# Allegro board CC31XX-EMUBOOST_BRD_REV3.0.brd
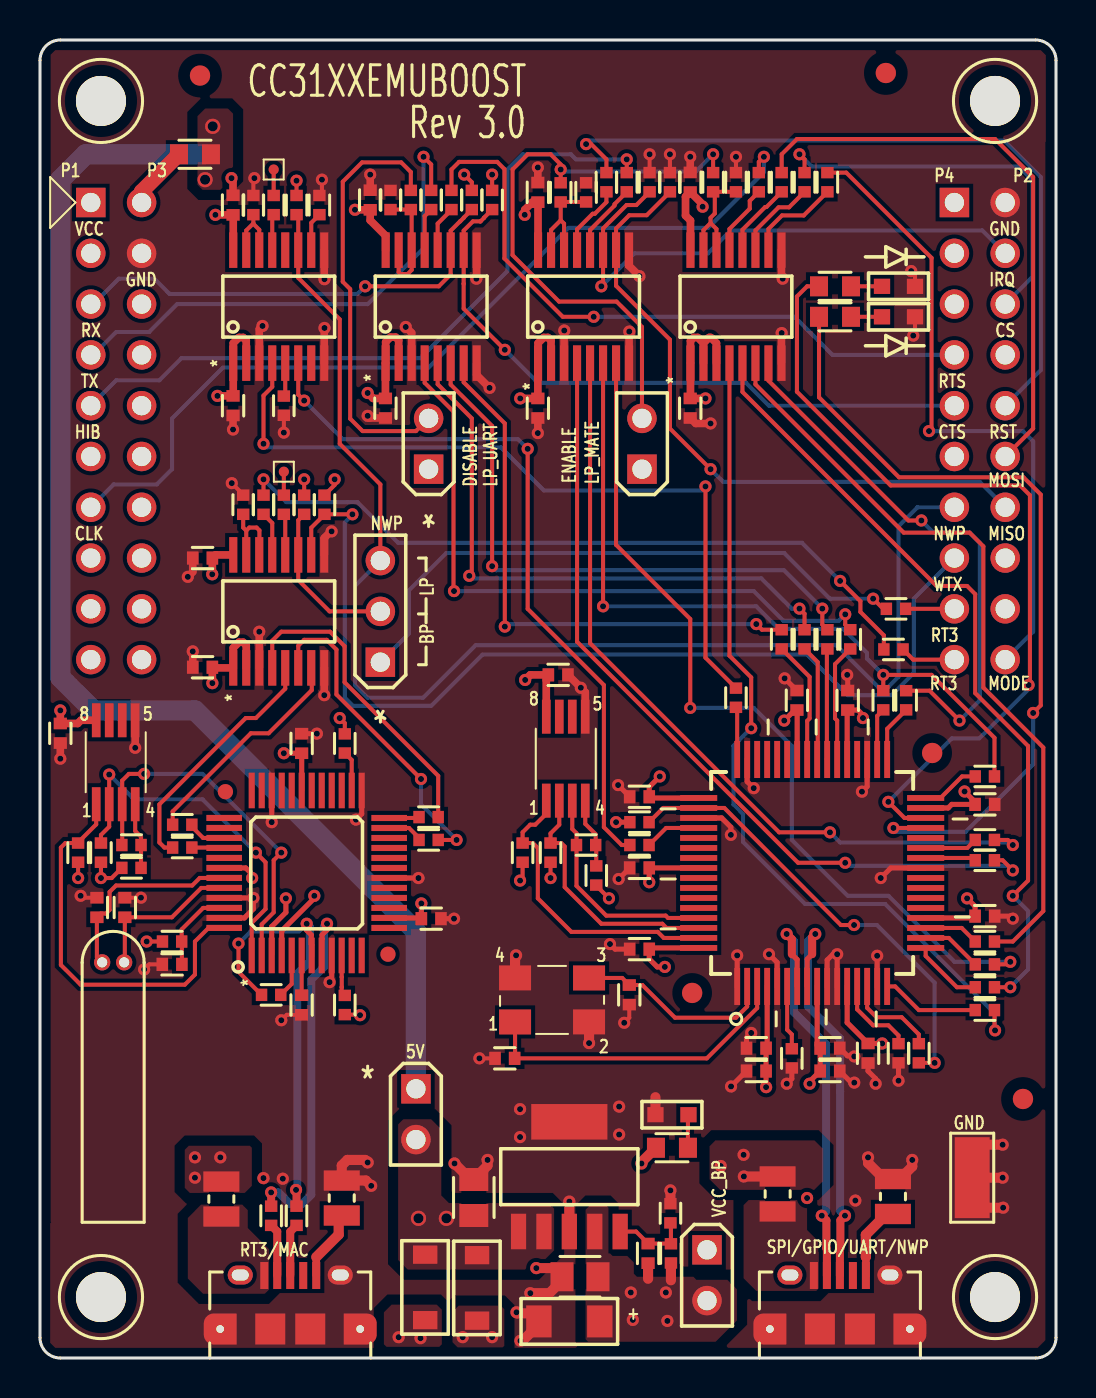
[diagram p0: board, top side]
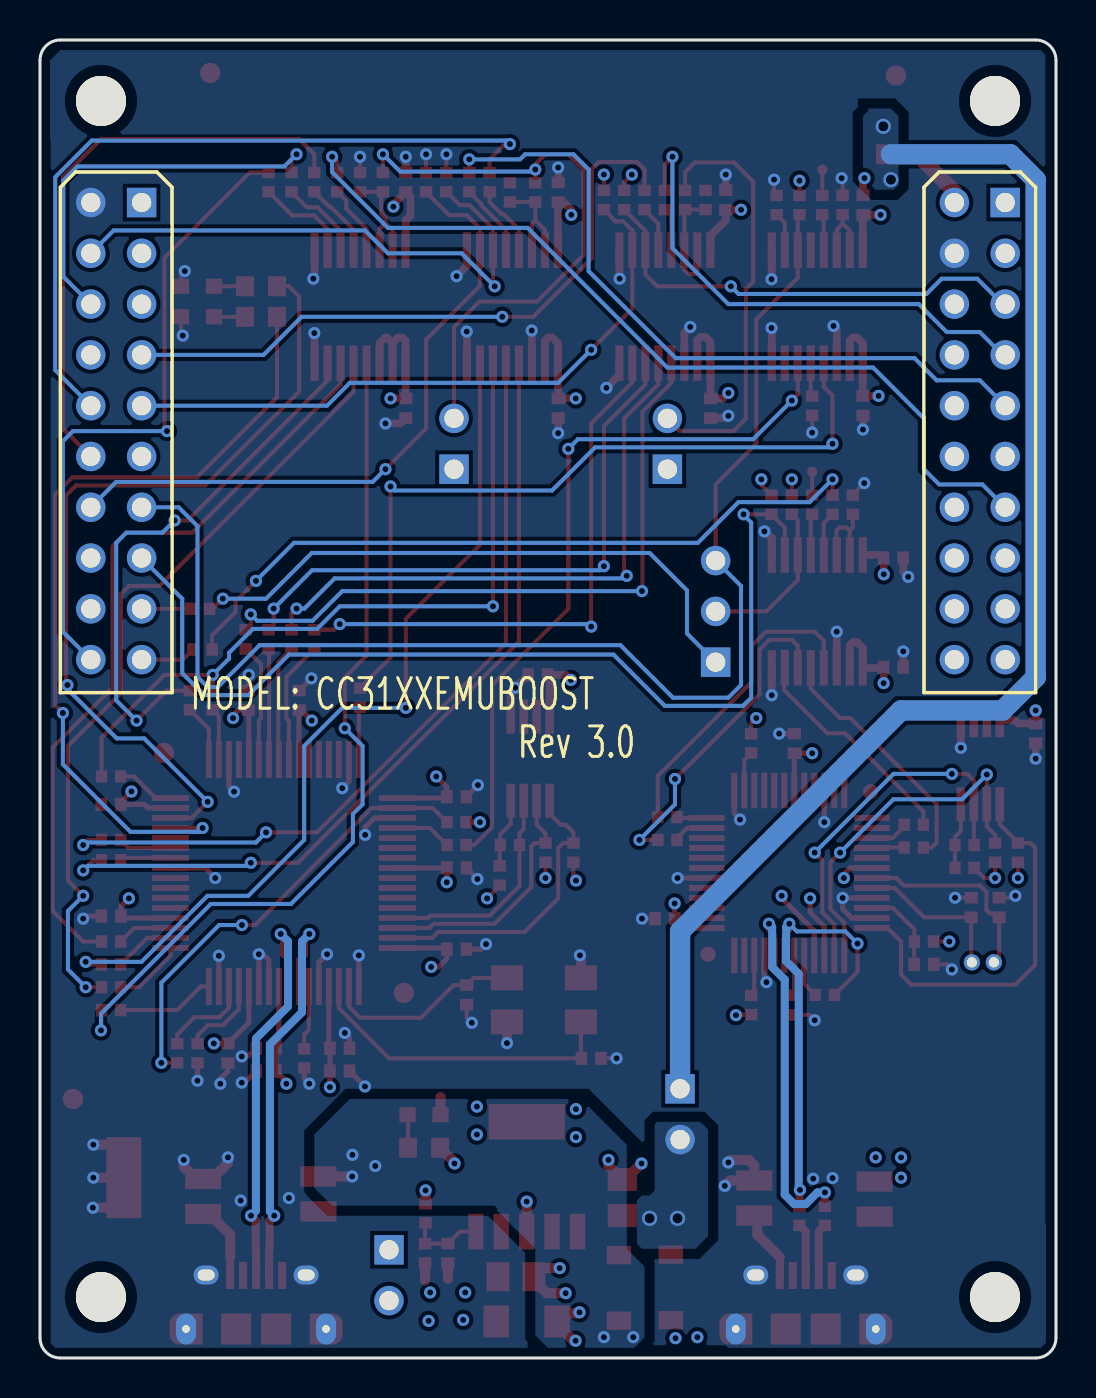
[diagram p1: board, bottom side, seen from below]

Outline 50.8 x 65.91 mm; copper layers: TOP, GND, PWR, BOTTOM. Coordinates in mm from the lower left corner of the outline.
Outline path: 0,64.9 arc(0.3,65.62) 1.02,65.91 49.78,65.91 arc(50.5,65.62) 50.8,64.9 50.8,1.02 arc(50.5,0.3) 49.78,0 1.02,0 arc(0.3,0.3) 0,1.02 0,64.9

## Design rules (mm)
net group DIFFPAIR0: nets N02098 N227919
net group DIFFPAIR1: nets N232899 N233111
net group DIFFPAIR2: nets N233117 N233261
nets with their own width: min track width 1.524; nets N226875 N230114 N408257

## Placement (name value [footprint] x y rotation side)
C1  0.1uF  [CC0402]  32.51 58.8 90 top
C2  0.1uF  [CC0402]  24.89 58.29 90 top
C3  0.1uF  [CC0402]  16.51 57.91 90 top
C4  0.1uF  [CC0402]  9.65 57.66 90 top
C5  0.1uF  [CC0402]  9.65 47.62 270 top
C6  0.1uF  [CC0402]  17.27 47.5 270 top
C7  0.1uF  [CC0402]  24.89 47.5 270 top
C8  0.1uF  [CC0402]  32.51 47.5 270 top
C9  0.1uF  [CC0402]  25.91 34.16 0 top
C10  0.1uF  [CC0402]  37.85 32.89 90 top
C11  0.1uF  [CC0402]  40.39 32.89 90 top
C12  0.1uF  [CC0402]  8.13 40.01 180 top
C13  0.1uF  [CC0402]  29.97 28.07 180 top
C14  0.1uF  [CC0402]  47.24 27.69 0 top
C15  0.1uF  [CC0402]  8.13 34.54 180 top
C16  0.1uF  [CC0402]  29.97 24.51 180 top
C17  0.1uF  [CC0402]  1.02 31.24 270 top
C18  0.1uF  [CC0402]  13.08 30.73 90 top
C19  0.1uF  [CC0402]  47.24 22.1 0 top
C20  0.1uF  [CC0402]  29.97 20.45 180 top
C21  27pF  [CC0402]  29.46 18.16 270 top
C22  0.1uF  [CC0402]  35.81 15.49 180 top
C23  0.1uF  [CC0402]  39.5 15.49 0 top
C24  4.7uF  [CC0402]  41.4 15.24 270 top
C25  27pF  [CC0402]  2.84 22.53 90 top
C26  27pF  [CC0402]  4.24 22.53 90 top
C27  0.1uF  [CC0402]  19.56 21.97 0 top
C28  4.7uF  [CC0402]  35.81 14.35 180 top
C29  4.7uF  [CC0402]  39.5 14.35 0 top
C30  0.1uF  [CC0402]  6.6 19.68 180 top
C31  27pF  [CC0402]  23.24 14.99 180 top
C32  33000 pF  [CC0402]  13.08 17.65 270 top
C33  10uF  [CC0805]  21.69 8.03 90 top
C34  15pF  [CC0402]  30.4 5.23 90 top
C35  10uF  [CC0805]  27 4.06 180 top
C36  100 uF  [TANT_1206]  26.47 1.83 180 top
D1  -  [LED_0603]  42.93 53.59 0 top
D2  -  [LED_0603]  42.93 52.07 0 top
D3  LED  [LED_0603]  31.6 12.17 180 top
D4  MBR130_SOD-123_2P  [SOD_123FL]  19.26 3.53 90 top
D5  MBR130_SOD-123_2P  [SOD_123FL]  21.85 3.51 90 top
FB1  FB  [INDC0805]  36.88 8.2 90 top
FB2  FB  [INDC0805]  42.65 8.08 270 top
FB3  FB  [INDC0805]  15.09 8 270 top
FB4  FB  [INDC0805]  9.07 7.95 90 top
J1  HEADER_2  [HDR_THVT_1X2_100_M]  19.43 44.45 180 top
J2  HEADER_2  [HDR_THVT_1X2_100_M]  30.1 44.45 180 top
J3  HEADER_3  [HDR_THVT_1X3_100_M]  17.02 34.8 180 top
J4  HEADER_2  [HDR_THVT_1X2_100_M]  33.35 5.41 0 top
J5  CONN_MICRO_USB  [FCI_10118194-0001]  12.51 1.54 0 top
J6  CONN_MICRO_USB  [FCI_10118194-0001]  39.99 1.54 0 top
J7  CONN_RCPT_10x2  [HDR_THVT_2X10_100_F]  45.72 57.78 180 bottom
J8  CONN_RCPT_10x2  [HDR_THVT_2X10_100_F]  2.54 57.78 180 bottom
J22  HEADER_2  [HDR_THVT_1X2_100_M]  18.8 13.46 0 top
NOREF  -  []  0.99 0 90 top
NOREF#2  -  [unnamed#2]  3.05 3.05 0 top
NOREF#3  -  [unnamed#2]  49.15 12.95 0 top
NOREF#4  -  [unnamed#2]  47.75 3.05 0 top
NOREF#5  -  [unnamed#2]  8 64.14 0 top
NOREF#6  -  [unnamed#2]  3.05 62.87 0 top
NOREF#7  -  []  0 64.9 0 top
NOREF#8  -  [unnamed#2]  47.75 62.87 0 top
NOREF#9  -  [unnamed#2]  42.29 64.26 0 top
R1  0.1  [RC0603]  7.75 60.2 0 top
R2  33  [RC0402]  28.32 58.8 90 top
R3  33  [RC0402]  29.34 58.8 90 top
R4  100k  [RC0402]  30.48 58.8 90 top
R5  100k  [RC0402]  31.5 58.8 90 top
R6  0 R  [RC0402]  33.66 58.8 90 top
R7  10k  [RC0402]  34.8 58.8 90 top
R8  33  [RC0402]  35.94 58.8 90 top
R9  33  [RC0402]  37.08 58.8 90 top
R10  33  [RC0402]  38.23 58.8 90 top
R11  33  [RC0402]  39.37 58.8 90 top
R12  0 R  [RC0402]  26.04 58.29 90 top
R13  10k  [RC0402]  27.3 58.29 90 top
R14  10k  [RC0402]  17.53 57.91 90 top
R15  0 R  [RC0402]  18.54 57.91 90 top
R16  33  [RC0402]  19.56 57.91 90 top
R17  33  [RC0402]  20.57 57.91 90 top
R18  100k  [RC0402]  21.59 57.91 90 top
R19  100k  [RC0402]  22.61 57.91 90 top
R20  10k  [RC0402]  10.67 57.66 90 top
R21  33  [RC0402]  11.68 57.66 90 top
R22  100k  [RC0402]  12.83 57.66 270 top
R23  100k  [RC0402]  13.97 57.66 90 top
R24  330  [RC0603]  39.75 53.59 0 top
R25  330  [RC0603]  39.75 52.07 0 top
R26  100k  [RC0402]  12.19 47.62 270 top
R29  0 R  [RC0402]  37.08 35.94 90 top
R30  0 R  [RC0402]  38.23 35.94 90 top
R31  0 R  [RC0402]  39.37 35.94 90 top
R32  0 R  [RC0402]  40.51 35.94 90 top
R33  10k  [RC0402]  10.16 42.67 90 top
R34  33  [RC0402]  11.18 42.67 90 top
R35  33  [RC0402]  12.19 42.67 90 top
R36  100k  [RC0402]  13.21 42.67 270 top
R37  100k  [RC0402]  14.22 42.67 270 top
R38  0 R  [RC0402]  34.8 33.02 90 top
R39  0 R  [RC0402]  42.16 32.89 90 top
R40  0 R  [RC0402]  43.31 32.89 90 top
R41  0 R  [RC0402]  47.24 29.08 0 top
R42  0 R  [RC0402]  29.97 26.8 180 top
R43  0 R  [RC0402]  47.24 25.91 0 top
R44  2.2K  [RC0402]  27.3 25.65 180 top
R45  0 R  [RC0402]  29.97 25.65 180 top
R46  10k  [RC0402]  24.13 25.27 270 top
R47  10k  [RC0402]  25.53 25.27 270 top
R48  0 R  [RC0402]  47.24 24.89 0 top
R49  10k  [RC0402]  27.81 24.13 270 top
R50  0 R  [RC0402]  47.24 20.83 0 top
R51  0 R  [RC0402]  47.24 19.68 0 top
R52  0 R  [RC0402]  19.43 27.05 0 top
R53  0 R  [RC0402]  7.11 26.67 180 top
R54  0 R  [RC0402]  47.24 18.54 0 top
R55  0 R  [RC0402]  19.43 25.91 0 top
R56  2.2K  [RC0402]  4.57 25.65 180 top
R57  0 R  [RC0402]  7.11 25.53 180 top
R58  10k  [RC0402]  1.91 25.27 90 top
R59  10k  [RC0402]  3.05 25.27 90 top
R60  0 R  [RC0402]  47.24 17.4 0 top
R61  10k  [RC0402]  4.57 24.51 0 top
R62  10k  [RC0402]  15.24 30.73 270 top
R63  0 R  [RC0402]  42.93 15.24 90 top
R64  1K  [RC0402]  43.94 15.24 90 top
R65  12K  [RC0402]  37.59 14.99 90 top
R66  470  [RC0402]  6.6 20.83 0 top
R67  2.2K  [RC0402]  11.56 18.16 0 top
R68  10k  [RC0402]  15.24 17.65 90 top
R69  270  [RC0603]  31.6 10.52 0 top
R70  30.1K  [RC0402]  31.52 7.24 270 top
R71  28  [RC0402]  11.56 7.11 90 top
R72  28  [RC0402]  12.83 7.11 90 top
R73  51K  [RC0402]  31.55 5.23 270 top
R74  DNP  [RC0402]  42.8 37.47 0 top
R75  DNP  [RC0402]  42.67 35.43 0 top
TP1  SMD  [TP_SMD_RND_0P5MM]  11.68 59.44 0 top
TP2  SMD  [TP_SMD_RND_0P5MM]  12.19 44.32 0 top
TP3  TP_1206  [TP_RCW1206]  46.61 9.02 90 top
U1  SN74AVC4T245PW  [TSSOP_16_201X177_26]  11.94 52.58 90 top
U2  SN74AVC4T245PW  [TSSOP_16_201X177_26]  19.56 52.58 90 top
U3  SN74AVC4T245PW  [TSSOP_16_201X177_26]  27.18 52.58 90 top
U4  SN74AVC4T245PW  [TSSOP_16_201X177_26]  34.8 52.58 90 top
U5  93LC46B-I/MS  [TI_MSOP8_0P65_3]  26.29 29.97 0 top
U6  SN74AVC4T245PW  [TSSOP_16_201X177_26]  11.94 37.34 90 top
U7  FT4232H  [TI_IC_LQFP64_0P5_10X10]  38.61 24.26 90 top
U8  93LC46B-I/MS  [TI_MSOP8_0P65_3]  3.78 29.79 0 top
U9  FT2232D  [QFP_48_284X284_20]  13.34 24.26 0 top
U10  TPS79601  [SOT_223_6_TG]  27.1 9.07 0 top
Y1  ECS-120-20-30B-TR  [TI_XTAL4_ECS-53B]  25.6 17.91 0 top
Y2  CRYSTAL  [XTAL_2P_TH_1P1MMP]  4.21 19.79 180 top

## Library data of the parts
C1-C8 C12 C15 C17 C18 C24 C27-C30 = C
C9-C11 C13 C14 C16 C19-C23 C25 C26 C31-C35 = CAP
C36 = CAP_POL
D1-D3 = LED
D4 D5 = MBR130_SOD-123_2P
FB1-FB4 = FERRITE_BEAD
J1 J2 J4 J22 = HEADER_1X2
J3 = HEADER_3
J5 J6 = CONN_MICRO_USB_5P_6G
J7 J8 = CONN_RCPT_0
R1 R6 R7 R12-R15 R20 R24 R25 R29-R33 R38-R73 = RESISTOR
R2-R5 R8-R11 R16-R19 R21-R23 R26 R34-R37 R74 R75 = R
TP1 TP2 = TP_SMD_RND_0P5MM
TP3 = TP_1206
U1-U4 U6 = SN74AVC4T245PW
U5 U8 = EEPROM-93C46B_4
U7 = FT4232H
U9 = FT2232_LQFP_48P
U10 = TPS79601_SOT-223_6P
Y1 = ZTA_0
Y2 = CRYSTAL

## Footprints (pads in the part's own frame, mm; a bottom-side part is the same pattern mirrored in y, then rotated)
CC0402
  rect 0.58x0.66 smd: 1(-0.49,0) 2(0.49,0)
CC0805
  rect 1.15x1.45 smd: 1(-0.9,0) 2(0.9,0)
FCI_10118194-0001
  rect 0.4x1.35 smd: 1(-1.3,2.59) 2(-0.65,2.59) 3(0,2.59) 4(0.65,2.59) 5(1.3,2.59)
  oval 1.25x0.95 hole 0.85x0.55: G1(-2.5,2.615) G2(2.5,2.615)
  custom 0.388x0.388 hole 1.15x0.5: G3(-3.5,-0.085) G6(3.5,-0.085)
  rect 1.5x1.55 smd: G4(-1,-0.085) G5(1,-0.085)
HDR_THVT_1X2_100_M
  rect 1.473x1.473 hole 0.965: 1(0,0)
  round 1.473 hole 0.965: 2(0,-2.54)
HDR_THVT_1X3_100_M
  rect 1.473x1.473 hole 0.965: 1(0,0)
  round 1.473 hole 0.965: 2(0,-2.54) 3(0,-5.08)
HDR_THVT_2X10_100_F
  rect 1.473x1.473 hole 0.965: 1(0,0)
  round 1.473 hole 0.965: 2(-2.54,0) 3(0,-2.54) 4(-2.54,-2.54) 5(0,-5.08) 6(-2.54,-5.08) 7(0,-7.62) 8(-2.54,-7.62) 9(0,-10.16) 10(-2.54,-10.16) 11(0,-12.7) 12(-2.54,-12.7) 13(0,-15.24) 14(-2.54,-15.24) 15(0,-17.78) 16(-2.54,-17.78) 17(0,-20.32) 18(-2.54,-20.32) 19(0,-22.86) 20(-2.54,-22.86)
INDC0805
  rect 1.016x1.8 smd: 1(-0.875,0) 2(0.875,0)
LED_0603
  rect 0.813x0.762 smd: 1(-0.826,0) 2(0.826,0)
QFP_48_284X284_20
  round 0.762 smd: (-4.064,4.064) (4.064,-4.064)
  rect 0.305x1.778 smd: 1(-2.75,-4.125) 2(-2.25,-4.125) 3(-1.75,-4.125) 4(-1.25,-4.125) 5(-0.751,-4.125) 6(-0.251,-4.125) 7(0.249,-4.125) 8(0.749,-4.125) 9(1.249,-4.125) 10(1.749,-4.125) 11(2.249,-4.125) 12(2.749,-4.125) 25(2.75,4.125) 26(2.25,4.125) 27(1.75,4.125) 28(1.25,4.125) 29(0.751,4.125) 30(0.251,4.125) 31(-0.249,4.125) 32(-0.749,4.125) 33(-1.249,4.125) 34(-1.749,4.125) 35(-2.249,4.125) 36(-2.749,4.125)
  rect 1.778x0.305 smd: 13(4.125,-2.75) 14(4.125,-2.25) 15(4.125,-1.75) 16(4.125,-1.25) 17(4.125,-0.751) 18(4.125,-0.251) 19(4.125,0.249) 20(4.125,0.749) 21(4.125,1.249) 22(4.125,1.749) 23(4.125,2.249) 24(4.125,2.749) 37(-4.125,2.75) 38(-4.125,2.25) 39(-4.125,1.75) 40(-4.125,1.25) 41(-4.125,0.751) 42(-4.125,0.251) 43(-4.125,-0.249) 44(-4.125,-0.749) 45(-4.125,-1.249) 46(-4.125,-1.749) 47(-4.125,-2.249) 48(-4.125,-2.749)
RC0402
  rect 0.57x0.62 smd: 1(-0.48,0) 2(0.48,0)
RC0603
  rect 0.9x1 smd: 1(-0.8,0) 2(0.8,0)
SOD_123FL
  rect 0.914x1.219 smd: 1(-1.638,0) 2(1.638,0)
SOT_223_6_TG
  rect 0.762x1.778 smd: 1(-3.175,-2.743) 2(-1.905,-2.743) 3(-0.635,-2.743) 4(0.635,-2.743) 5(1.905,-2.743)
  rect 3.81x1.778 smd: 6(-0.635,2.743)
TANT_1206
  rect 1.27x1.6 smd: 1(-1.524,0) 2(1.524,0)
TI_IC_LQFP64_0P5_10X10
  round 1.016 smd: (-6,6) (6,-6)
  rect 1.854x0.292 smd: 1(-5.675,3.75) 2(-5.675,3.25) 3(-5.675,2.75) 4(-5.675,2.25) 5(-5.675,1.75) 6(-5.675,1.25) 7(-5.675,0.75) 8(-5.675,0.25) 9(-5.675,-0.25) 10(-5.675,-0.75) 11(-5.675,-1.25) 12(-5.675,-1.75) 13(-5.675,-2.25) 14(-5.675,-2.75) 15(-5.675,-3.25) 16(-5.675,-3.75) 33(5.675,-3.75) 34(5.675,-3.25) 35(5.675,-2.75) 36(5.675,-2.25) 37(5.675,-1.75) 38(5.675,-1.25) 39(5.675,-0.75) 40(5.675,-0.25) 41(5.675,0.25) 42(5.675,0.75) 43(5.675,1.25) 44(5.675,1.75) 45(5.675,2.25) 46(5.675,2.75) 47(5.675,3.25) 48(5.675,3.75)
  rect 0.292x1.854 smd: 17(-3.75,-5.675) 18(-3.25,-5.675) 19(-2.75,-5.675) 20(-2.25,-5.675) 21(-1.75,-5.675) 22(-1.25,-5.675) 23(-0.75,-5.675) 24(-0.25,-5.675) 25(0.25,-5.675) 26(0.75,-5.675) 27(1.25,-5.675) 28(1.75,-5.675) 29(2.25,-5.675) 30(2.75,-5.675) 31(3.25,-5.675) 32(3.75,-5.675) 49(3.75,5.675) 50(3.25,5.675) 51(2.75,5.675) 52(2.25,5.675) 53(1.75,5.675) 54(1.25,5.675) 55(0.75,5.675) 56(0.25,5.675) 57(-0.25,5.675) 58(-0.75,5.675) 59(-1.25,5.675) 60(-1.75,5.675) 61(-2.25,5.675) 62(-2.75,5.675) 63(-3.25,5.675) 64(-3.75,5.675)
TI_MSOP8_0P65_3
  rect 0.432x1.7 smd: 1(-0.975,-2.1) 2(-0.325,-2.1) 3(0.325,-2.1) 4(0.975,-2.1) 5(0.975,2.1) 6(0.325,2.1) 7(-0.325,2.1) 8(-0.975,2.1)
TI_XTAL4_ECS-53B
  rect 1.6x1.25 smd: 1(-1.85,-1.1) 2(1.85,-1.1) 3(1.85,1.1) 4(-1.85,1.1)
TP_RCW1206
  rect 4.05x1.75 smd: 1(0,0)
TP_SMD_RND_0P5MM
  round 0.508 smd: 1(0,0)
TSSOP_16_201X177_26
  rect 1.778x0.406 smd: 1(-2.825,2.275) 2(-2.825,1.625) 3(-2.825,0.975) 4(-2.825,0.325) 5(-2.825,-0.325) 6(-2.825,-0.975) 7(-2.825,-1.625) 8(-2.825,-2.275) 9(2.825,-2.275) 10(2.825,-1.625) 11(2.825,-0.975) 12(2.825,-0.325) 13(2.825,0.325) 14(2.825,0.975) 15(2.825,1.625) 16(2.825,2.275)
unnamed#2
  round 2.5 hole 3.2 unplated: (0,0)
XTAL_2P_TH_1P1MMP
  round 0.813 hole 0.508: 1(0,0) 2(1.1,0)

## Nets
GND: C1.2 C2.2 C3.2 C4.2 C5.2 C6.2 C7.2 C8.2 C9.2 C10.2 C11.2 C12.2 C13.2 C14.2 C15.2 C16.2 C17.2 C18.2 C19.2 C20.2 C21.2 C22.2 C23.2 C24.2 C25.2 C26.2 C27.2 C28.2 C29.2 C30.2 C31.2 C32.2 C33.2 C35.2 C36.2 D1.2(CATHODE) D2.2(CATHODE) D3.2(CATHODE) FB2.1 FB3.1 J5.G1 J5.G2 J5.G3 J5.G4 J5.G5 J5.G6 J6.G1 J6.G2 J6.G3 J6.G4 J6.G5 J6.G6 J7.2 J8.4 R4.2 R5.2 R7.2 R13.2 R14.2 R20.2 R23.2 R26.2 R33.2 R63.1 R65.1 R70.1 TP3.1 U1.3(2DIR) U1.8(GND1) U1.9(GND2) U2.3(2DIR) U2.8(GND1) U2.9(GND2) U3.3(2DIR) U3.8(GND1) U3.9(GND2) U4.8(GND1) U4.9(GND2) U5.5(GND) U6.3(2DIR) U6.8(GND1) U6.9(GND2) U7.1(GND1) U7.5(GND2) U7.10(AGND) U7.11(GND3) U7.15(GND4) U7.25(GND5) U7.35(GND6) U7.47(GND7) U7.51(GND8) U8.5(GND) U9.9(GND#9) U9.18(GND#18) U9.25(GND#25) U9.34(GND#34) U9.45(AGND) U9.47(TEST) U10.3(GND) U10.6(TAB) Y1.2 Y1.4
VCC_5V: J22.1 R1.2
VCC_BP: C1.1 C2.1 C3.1 C4.1 C12.1 J4.1 J8.1 R18.2 R19.2 R22.1 R36.1 R37.1 R69.1 U1.16(VCCB) U2.16(VCCB) U3.16(VCCB) U4.16(VCCB) U6.16(VCCB)
VCC_USB5V_DUAL: D4.1(ANODE) FB4.2 R66.1 U9.3(VCC#3) U9.42(VCC#42)
VCC_USB5V_QUAD: D5.1(ANODE) FB1.2
FTDI_DUAL_A_RX_BP: J3.2 R36.2 U6.11(2B1)
FTDI_DUAL_A_TX_BP: R34.2 R75.1
FTDI_DUAL_B_RX_BP: J7.15 R37.2 U6.10(2B2)
FTDI_QUAD_A_SPI_CLK_3V3: R60.2 U4.4(1A1)
FTDI_QUAD_A_SPI_CLK_BP: J8.13 R8.2
FTDI_QUAD_A_SPI_CS_3V3: R50.2 U4.6(2A1)
FTDI_QUAD_A_SPI_CS_BP: J7.6 R10.2
FTDI_QUAD_A_SPI_MISO_3V3: R51.2 U3.7(2A2)
FTDI_QUAD_A_SPI_MISO_BP: J7.14 R5.1 U3.10(2B2)
FTDI_QUAD_A_SPI_MOSI_3V3: R54.2 U4.5(1A2)
FTDI_QUAD_A_SPI_MOSI_BP: J7.12 R9.2
FTDI_QUAD_B00_NRESET_3V3: R48.2 U3.4(1A1)
FTDI_QUAD_B00_NRESET_BP: J7.10 R2.2
FTDI_QUAD_B01_NHIB_3V3: R43.2 U3.5(1A2)
FTDI_QUAD_B01_NHIB_BP: J8.9 R3.2
FTDI_QUAD_B06_MODE_3V3: R40.2 U4.7(2A2)
FTDI_QUAD_B06_MODE_BP: J7.20 R11.2
FTDI_QUAD_B07_IRQ_3V3: R39.2 R41.2 U3.6(2A1)
FTDI_QUAD_B07_IRQ_BP: J7.4 R4.1 U3.11(2B1)
FTDI_QUAD_C_U_CTS_3V3: R29.2 U2.7(2A2)
FTDI_QUAD_C_U_CTS_BP: J7.9 R19.1 U2.10(2B2)
FTDI_QUAD_C_U_RTS_3V3: R30.2 U2.5(1A2)
FTDI_QUAD_C_U_RTS_BP: J7.7 R17.2
FTDI_QUAD_C_U_RX_3V3: R31.2 U2.6(2A1)
FTDI_QUAD_C_U_RX_BP: J8.5 R18.1 U2.11(2B1)
FTDI_QUAD_C_U_TX_3V3: R32.2 U2.4(1A1)
FTDI_QUAD_C_U_TX_BP: J8.7 R16.2
FTDI_QUAD_D_U_RX_3V3: R45.2 U1.6(2A1)
FTDI_QUAD_D_U_RX_BP: J3.3 J7.13 R22.2 U1.11(2B1)
FTDI_QUAD_D_U_TX_3V3: R38.2 U1.4(1A1)
LED1: R25.1 U7.29(B - \\C\T\S\/TMS/CS)
LED2: R24.1 U7.30(B - GPIOL0)
LP_MATE_EN: J2.2 R6.2 R12.2
LP_UART_DIS: J1.2 R15.2
USB_1V8: C11.1 C13.1 C20.1 C24.1 U7.12(VCORE3) U7.37(VCORE2) U7.49(VREGOUT) U7.64(VCORE1)
USB_3V3: C5.1 C6.1 C7.1 C8.1 C9.1 C10.1 C14.1 C15.1 C16.1 C17.1 C18.1 C19.1 C22.1 C23.1 C27.1 C28.1 C29.1 C34.1 C35.1 C36.1 J1.1 J2.1 J4.2 R42.2 R46.2 R47.2 R49.2 R58.1 R59.1 R61.1 R62.1 R68.1 R73.2 U1.1(VCCA) U1.2(1DIR) U2.1(VCCA) U2.2(1DIR) U3.1(VCCA) U3.2(1DIR) U4.1(VCCA) U4.2(1DIR) U4.3(2DIR) U5.8(VCC) U6.1(VCCA) U6.2(1DIR) U7.4(VPHY) U7.9(VPLL) U7.20(VCCIO4) U7.31(VCCIO3) U7.42(VCCIO2) U7.56(VCCIO1) U8.8(VCC) U9.4(RESET#) U9.14(VCCIOA) U9.31(VCCIOB) U10.4(OUT)
N01286: R44.1 R49.1 U5.4(DOUT)
N01352: R47.1 U5.2(CLK) U7.62(EECLK)
N01364: R65.2 U7.6(REF)
N01384: C21.1 U7.2(OSCI) Y1.3
N01506: R46.1 U5.1(CS) U7.63(EES)
N01570: C31.1 U7.3(OSCO) Y1.1
N01960: R44.2 U5.3(DIN) U7.61(EEDATA)
N02002: R63.2 U7.13(TEST)
N02098: J6.3(D+) U7.8(DP)
N02410: R42.1 R64.1 U7.50(VREGIN)
N02574: R64.2 U7.14(\\R\E\S\E\T)
N226875: FB1.1 J6.1(VCC)
N226931: FB2.2 J6.5(GND)
N227919: J6.2(D-) U7.7(DM)
N230114: FB4.1 J5.1(VCC)
N230138: FB3.2 J5.5(GND)
N230650: R56.1 R61.2 U8.4(DOUT)
N230686: R59.2 U8.2(CLK) U9.1(EESK)
N230722: R58.2 U8.1(CS) U9.48(EECS)
N230850: R56.2 U8.3(DIN) U9.2(EEDATA)
N232459: C26.1 U9.44(XTOUT) Y2.1
N232466: C25.1 U9.43(XTIN) Y2.2
N232899: J5.2(D-) R71.1
N233111: J5.3(D+) R72.1
N233117: R71.2 U9.8(USBDM)
N233261: R67.1 R72.2 U9.7(USBDP)
N233354: C32.1 U9.6(3V3OUT)
N233745: C30.1 R66.2 U9.46(AVCC)
N234481: R67.2 U9.5(RSTOUT#)
N234666: R62.2 U9.26(SI/WUB)
N234693: R68.2 U9.10(SI/WUA)
N238775: R48.1 U7.26(B - TXD/TCK/SK)
N238779: R43.1 U7.27(B - RXD/TDI/DO)
N238807: R41.1 U7.32(B - GPIOL1)
N238860: R32.1 U7.38(C - TXD)
N238864: R31.1 U7.39(C - RXD)
N238868: R30.1 U7.40(C - \\R\T\S)
N238872: R29.1 U7.41(C - \\C\T\S\)
N238924: R38.1 U7.48(D - TXD)
N238928: R45.1 U7.52(D - RXD)
N239386: R39.1 U7.34(B - GPIOL3)
N272217: R53.2 U6.7(2A2)
N292019: R14.1 R15.1 U2.14(2O\E\) U2.15(1O\E\)
N292933: D1.1(ANODE) R24.2
N292961: D2.1(ANODE) R25.2
N294895: R6.1 R7.1 U4.14(2O\E\) U4.15(1O\E\)
N295733: R12.1 R13.1 U3.14(2O\E\) U3.15(1O\E\)
N296706: R20.1 U1.14(2O\E\) U1.15(1O\E\)
N300466: R50.1 U7.19(A - \\C\T\S\/TMS/CS)
N300468: R51.1 U7.18(A - \\R\T\S\/TDO/DI)
N300470: R54.1 U7.17(A - RXD/TDI/DO)
N300472: R60.1 U7.16(A - TXD/TCK/SK)
N302094: R53.1 U9.39(BDBUS1)
N302821: R23.1 U1.10(2B2)
N310009: R33.1 U6.14(2O\E\) U6.15(1O\E\)
N310225: R55.2 U6.6(2A1)
N314694: R26.1 U1.5(1A2)
N325704: R40.1 U7.33(B - GPIOL2)
N329899: R52.2 U6.4(1A1)
N329904: R57.2 U6.5(1A2)
N334866: R17.1 U2.12(1B2)
N372295: R34.1 U6.13(1B1)
N372693: R52.1 U9.24(ADBUS0)
N372697: R55.1 U9.23(ADBUS1)
N381832: R35.1 U6.12(1B2)
N381852: R57.1 U9.40(BDBUS0)
N393401: R21.1 U1.13(1B1)
N393405: R21.2 TP1.1
N393465: R2.1 U3.13(1B1)
N393469: R3.1 U3.12(1B2)
N393541: R16.1 U2.13(1B1)
N393687: R11.1 U4.10(2B2)
N393689: R10.1 U4.11(2B1)
N393691: R9.1 U4.12(1B2)
N393693: R8.1 U4.13(1B1)
N407737: J8.2 R1.1
N408139: J3.1 R74.1
N408257: C33.1 D4.2(CATHODE) D5.2(CATHODE) J22.2 U10.1(EN) U10.2(IN)
N408297: C34.2 R70.2 R73.1 U10.5(FB)
N408485: D3.1(ANODE) R69.2
N415889: R35.2 TP2.1
N437475: J7.19 R75.2
N437479: J7.17 R74.2

Pads without a net: J5 4; J6 4; J7 1 3 5 8 11 16 18; J8 3 6 8 10 11 12 14 15 16 17 18 19 20; U1 7 12; U5 6 7; U7 21 22 23 24 28 36 43 44 45 46 53 54 55 57 58 59 60; U8 6 7; U9 11 12 13 15 16 17 19 20 21 22 27 28 29 30 32 33 35 36 37 38 41

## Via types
v1: diameter 0.762, hole 0.508, TOP to BOTTOM, 4 vias
v2: diameter 0.61, hole 0.305, TOP to BOTTOM, 215 vias

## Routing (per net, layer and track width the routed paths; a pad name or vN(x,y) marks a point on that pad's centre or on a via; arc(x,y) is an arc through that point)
GND: length 117.1
  TOP w0.203: v2(9.59,43.75) 10.16,43.18 R33.2 ; v2(43.66,51.13) 43.75,51.22 D2.2 ; R4.2 v2(30.48,60.2) ; R20.2 10.67,58.95 v2(10.72,59) ; C31.2 v2(21.97,14.99) ; v2(12.06,16.89) 12.34,17.16 C32.2 ; v2(2.03,23.11) 2.13,23.02 C25.2 ; v2(5.21,19.43) 5.46,19.68 C30.2 ; C21.2 29.46,17.02 v2(29.21,16.76) ; D1.2 43.75,54.29 43.69,54.36 v2(43.56,54.36) ; v2(14.1,58.93) 14.1,58.26 R23.2 ; C26.2 v2(5.05,23.02) ; v2(34.8,60.07) 34.8,60.07 R7.2 ; R5.2 v2(31.5,60.2) ; R26.2 v2(12.19,46.28)
  TOP w0.254: v2(37.34,13.72) 37.59,13.97 R65.1 ; C20.2 28.75,20.45 v2(28.5,20.7) ; C13.2 29.48,28.07 v2(28.91,28.65) ; U7.35 41.36,28.58 v2(41.1,28.32) ; v2(18.92,24) 17.46,24 U9.18 ; U7.51 34.08,27.01 34.54,26.54 v2(34.54,26.16) ; v2(41.78,13.72) 41.78,13.97 41.4,14.35 C24.2 ; U7.15 v2(41.86,20.12) ; U9.9 14.58,18.9 v2(14.48,18.8) ; v2(48.64,21.97) 48.51,22.1 C19.2 ; U7.10 39.36,19.9 39.65,20.19 v2(39.86,20.19) U7.11 ; U7.47 35.36,28.83 v2(35.69,28.5) ; C23.2 40.37,15.11 40.68,15.11 v2(40.71,15.08) ; v2(15.8,26.92) 16.09,27.21 U9.25 ; v2(28.93,23.95) 29.48,24.5 C16.2 ; C10.2 37.84,33.38 v2(37.23,33.99) ; C28.2 v2(34.55,13.58) ; v2(36.45,20.19) 36.86,19.78 U7.5 ; C22.2 35.32,16.02 v2(35.56,16.26) ; 44.28,24.51 42.54,24.51 v2(42.04,24) ; C29.2 40.57,13.77 v2(40.71,13.77) ; C11.2 40.39,34.04 40.36,34.06 v2(40.36,34.16) ; C27.2 v2(20.7,21.97) ; U9.47 10.22,22.01 10.67,22.46 v2(10.67,23.01) U9.45 ; R63.1 v2(42.93,13.87) ; C18.2 v2(13.84,31.22) ; U9.34 v2(11.59,26.8) ; U7.1 v2(34.86,20.13)
  TOP w0.381: C3.2 v2(16.51,59.18) ; U3.3 26.2,51.37 v2(26.21,51.38) ; U8.5 v2(4.76,30.52) ; C9.2 v2(27.04,33.52) 27.26,33.3 U5.5 ; v2(14.22,51.51) 14.21,51.5 U1.8 ; U6.8 v2(14.21,33.15) ; U4.8 37.07,51.25 v2(37.08,51.26) ; v2(11.13,51.61) 10.96,51.45 U1.3 ; U4.9 37.07,54.04 v2(37.13,53.98) ; v2(33.53,46.74) 32.78,46.74 C8.2 ; U3.9 29.45,54.62 v2(29.97,54.1) ; v2(14.58,41.34) 14.54,41.34 14.21,41.01 U6.9 ; C5.2 v2(9.65,46.43) ; U2.8 21.83,49.16 v2(22.48,48.51) ; v2(21.82,53.98) 21.83,53.99 U2.9 ; C17.2 v2(1.02,29.97) ; v2(14.22,53.95) 14.21,53.96 U1.9 ; C15.2 v2(7.64,35.34) ; v2(7.39,39.07) 7.64,39.31 C12.2 ; U2.3 18.58,51.27 v2(18.29,51.56) ; U6.3 v2(10.96,36.32) ; C7.2 v2(24.89,46.25) ; C2.2 v2(24.89,59.54) ; C6.2 16.49,47.01 v2(16.38,47.12) ; C4.2 9.65,58.93 v2(9.58,59) ; v2(29.46,51.33) 29.45,51.32 U3.8 ; C1.2 v2(32.51,60.07)
  TOP w0.505: v2(23.83,2.29) 23.88,2.24 24.54,2.24 C36.2 24.94,1.68 24.13,0.86 v2(24.02,0.86) ; TP3.1 v2(48.13,9.02) ; TP3.1 46.61,10.41 46.86,10.67 v2(48.13,10.67) ; TP3.1 46.61,7.87 46.97,7.52 v2(48.16,7.52) ; Y1.2 v2(27.45,15.75) ; v2(20.73,9.73) 21.53,8.93 C33.2 21.69,8.94 22.38,9.63 v2(22.38,9.91) ; Y1.4 23.75,20.09 v2(23.8,20.14) ; U10.3 v2(26.47,7.82) ; v2(16.38,9.78) 16.26,9.91 15.37,9.91 15.09,9.63 FB3.1 16.3,8.88 v2(16.56,8.61) ; v2(43.61,9.91) 43.61,9.58 42.99,8.95 FB2.1 42.2,8.95 41.4,9.75 v2(41.4,10.03) ; R70.1 v2(31.52,8.38) ; D3.2 30.77,13.04 ; v2(24.52,3.24) 25.47,3.24 26.1,3.88 C35.2 25.67,4.5 v2(24.82,4.5)
  vias: v2(11.17,9) v2(12.14,8.97) v2(24,12.45) v2(24,11.05) v2(28.96,12.57) v2(28.96,11.18) v2(38.35,8) v2(40.77,7.87)
VCC_5V: length 63.6
  BOTTOM w1.016: 8.26,60.2 2.29,60.2 1.02,58.93 1.02,34.04 2.67,32.38 7.75,32.38 18.8,21.34 J22.1
  vias: v1(8.26,58.93) v1(8.64,61.59)
VCC_BP: length 20.6
  TOP w0.203: R19.2 v2(22.61,59.18) ; v2(21.21,59.18) 21.59,58.8 R18.2 ; v2(14.73,43.94) 14.73,43.66 R37.1 ; R36.1 v2(13.21,43.94) ; R22.1 v2(12.83,58.88)
  TOP w0.381: v2(24.24,57.17) 24.24,57.42 24.62,57.8 C2.1 24.9,57.79 U3.16 ; U2.16 17.28,56.12 16.51,56.9 C3.1 v2(15.75,57.42) ; U1.16 9.66,57.16 C4.1 v2(8.77,57.17) ; v2(33.13,57.58) 33.13,57.69 32.51,58.31 C1.1 32.28,58.08 32.28,57.13 32.52,56.88 U4.16 ; U6.16 8.78,40.16 C12.1 8.62,39.2 v2(8.61,39.19)
  TOP w0.505: R69.1 30.07,9.79 v2(30.07,9.73)
VCC_USB5V_DUAL: length 5.7
  TOP w0.203: R66.1 v2(5.33,20.83)
  TOP w0.254: v2(12.29,22.99) 12.29,22.28 11.58,21.58 U9.3 ; v2(10.61,24) 10.54,24.07 10.54,24.25 10.29,24.51 U9.42
  vias: v2(7.75,10.03) v2(7.75,9.02) v2(9.02,10.03) v2(17.93,1.04) v2(19.02,0.99)
VCC_USB5V_QUAD: length 1.7
  TOP w0.505: FB1.2 v2(35.19,9.08)
  vias: v2(21.14,1.04) v2(22.61,1.04) v2(34.04,9.6) v2(35.18,10.16)
FTDI_DUAL_A_RX_BP: length 8.2
  TOP w0.203: R36.2 12.91,41.9 U6.11 12.91,38.9 14.48,37.34 J3.2
FTDI_DUAL_A_TX_BP: length 36.1
  TOP w0.203: R34.2 v2(11.18,43.94) ; v2(40.01,38.86) 41.02,37.85 41.02,37.31 42.19,36.14 R75.1
  BOTTOM w0.203: v2(40.01,38.86) 38.1,40.77 17.91,40.77 15.87,42.8 15.37,42.8 15.37,42.8 12.32,42.8 v2(11.18,43.94)
FTDI_DUAL_B_RX_BP: length 50.6
  TOP w0.203: U6.10 13.56,41.52 14.22,42.18 R37.2 v2(15.62,42.19)
  BOTTOM w0.203: v2(15.62,42.19) 15.62,42.16 15.24,41.78 15.24,33.02 15.65,32.61 19.56,32.61 22.12,35.18 38.35,35.18 40.39,33.15 42.58,33.15 43.69,34.25 43.69,37.97 J7.15
FTDI_QUAD_A_SPI_CLK_3V3: length 43
  TOP w0.203: v2(35.56,31.5) 35.56,34.04 34.47,35.12 U4.4 ; R60.2 47.72,16.41 v2(47.75,16.38)
  BOTTOM w0.203: v2(47.75,16.38) 47.75,17.21 42.26,22.71 40.56,22.71 38.25,22.71 35.15,25.81 35.15,27.2 34.67,27.69 34.67,30.61 v2(35.56,31.5)
FTDI_QUAD_A_SPI_CLK_BP: length 43.7
  TOP w0.203: v2(36.2,60.07) 35.94,59.82 R8.2
  BOTTOM w0.203: v2(36.2,60.07) 36.2,59.31 33.4,56.52 26.42,56.52 19.43,49.53 9.14,49.53 6.6,46.99 6.6,44.45 5.84,43.69 3.68,43.69 J8.13
FTDI_QUAD_A_SPI_CS_3V3: length 38.4
  TOP w0.203: R50.2 48.64,20.83 50.16,22.35 50.16,30.53 47.17,33.53 47.17,40.59 46.48,41.27 43.19,41.27 35.77,48.69 U4.6
FTDI_QUAD_A_SPI_CS_BP: length 20
  TOP w0.203: v2(37.97,60.2) 38.23,59.94 R10.2
  BOTTOM w0.203: v2(37.97,60.2) 38.58,59.59 48.93,59.59 49.63,58.89 49.63,54.08 J7.6
FTDI_QUAD_A_SPI_MISO_3V3: length 43.6
  TOP w0.203: R51.2 48.39,19.68 v2(48.51,19.81) ; U3.7 28.8,40.67 32.51,36.96 v2(32.51,32.51)
  BOTTOM w0.203: v2(48.51,19.81) 45.73,19.81 42.43,23.11 40.39,23.11 37.59,25.91 37.59,30.61 35.69,32.51 v2(32.51,32.51)
FTDI_QUAD_A_SPI_MISO_BP: length 33
  TOP w0.203: v2(33.53,44.45) 31.5,46.48 31.5,50.93 28.8,53.62 U3.10 28.8,56.49 29.46,57.15 30.34,57.15 31.5,58.31 R5.1
  BOTTOM w0.203: J7.14 46.99,43.81 34.16,43.81 v2(33.53,44.45)
FTDI_QUAD_A_SPI_MOSI_3V3: length 39.8
  TOP w0.203: U4.5 35.12,48.32 44.83,38.61 46.36,38.61 46.76,38.2 46.76,33.25 49.4,30.61 49.4,23.88 v2(48.64,23.11) ; R54.2 v2(48.51,18.54)
  BOTTOM w0.203: v2(48.51,18.54) 49.4,19.43 49.4,22.35 v2(48.64,23.11)
FTDI_QUAD_A_SPI_MOSI_BP: length 29.1
  TOP w0.203: R9.2 37.08,60.2 37.85,60.96 47.75,60.96 49.66,59.06 49.66,46.48 J7.12
FTDI_QUAD_B00_NRESET_3V3: length 41.6
  TOP w0.203: v2(48.64,24.38) 48.13,24.89 R48.2 ; v2(40.26,24.77) 37.9,24.77 26.85,35.82 U3.4
  BOTTOM w0.203: v2(40.26,24.77) 40.41,24.61 48.41,24.61 v2(48.64,24.38)
FTDI_QUAD_B00_NRESET_BP: length 37.7
  TOP w0.203: R2.2 28.32,59.94 27.56,60.71 v2(27.3,60.71)
  BOTTOM w0.203: v2(27.3,60.71) 27.48,60.88 48.21,60.88 50.04,59.05 50.04,49.4 J7.10
FTDI_QUAD_B01_NHIB_3V3: length 40.3
  TOP w0.203: U3.5 27.5,35.75 36.96,26.29 v2(39.5,26.29) ; R43.2 48.39,25.91 v2(48.64,25.65)
  BOTTOM w0.203: v2(39.5,26.29) 40.01,25.78 48.51,25.78 v2(48.64,25.65)
FTDI_QUAD_B01_NHIB_BP: length 35.7
  TOP w0.203: R3.2 v2(29.34,59.94)
  BOTTOM w0.203: J8.9 3.81,48.9 5.97,48.9 7.07,50 19.01,50 23.37,54.36 23.37,59.44 24.13,60.2 26.54,60.2 26.8,59.94 v2(29.34,59.94)
FTDI_QUAD_B06_MODE_3V3: length 27.4
  TOP w0.203: U4.7 36.42,48.88 43.42,41.88 v2(44.07,41.88) ; R40.2 44.48,33.37 v2(45.97,31.88)
  BOTTOM w0.203: v2(44.07,41.88) 44.68,41.27 46.48,41.27 46.99,40.77 46.99,32.89 v2(45.97,31.88)
FTDI_QUAD_B06_MODE_BP: length 32.6
  TOP w0.203: R11.2 40.31,59.28 44.58,55.02 44.58,46.48 v2(44.45,46.35)
  BOTTOM w0.203: v2(44.45,46.35) 49.15,46.35 49.66,45.85 49.66,36.32 J7.20
FTDI_QUAD_B07_IRQ_3V3: length 37.3
  TOP w0.203: v2(28.15,37.59) U3.6 ; R41.2 47.72,31.02 44.58,34.16 v2(42.16,34.16) R39.2
  BOTTOM w0.203: v2(42.16,34.16) 41.35,34.98 41.35,35.27 40.15,36.46 36.95,36.46 35.81,37.59 v2(28.15,37.59)
FTDI_QUAD_B07_IRQ_BP: length 27.8
  TOP w0.203: R4.1 29.82,57.66 29.33,57.66 28.15,56.49 U3.11 28.15,53.68 v2(28.07,53.59)
  BOTTOM w0.203: J7.4 47.12,56.39 34.54,56.39 33.4,55.24 29.72,55.24 v2(28.07,53.59)
FTDI_QUAD_C_U_CTS_3V3: length 28
  TOP w0.203: v2(35.81,36.7) 36.1,36.42 R29.2 ; v2(23.24,36.58) 23.24,46.74 21.18,48.79 U2.7
  BOTTOM w0.203: v2(35.81,36.7) 23.37,36.7 v2(23.24,36.58)
FTDI_QUAD_C_U_CTS_BP: length 32.3
  TOP w0.203: R19.1 22.2,57.03 22.2,57.02 22.03,56.84 22.02,56.84 21.64,56.84 21.18,56.38 U2.10 21.18,55.4 21.18,53.72 21.18,52.48 v2(23.24,50.42)
  BOTTOM w0.203: J7.9 36.45,47.62 35.31,48.77 24.89,48.77 v2(23.24,50.42)
FTDI_QUAD_C_U_RTS_3V3: length 29.7
  TOP w0.203: v2(21.46,39.12) 21.59,39.24 21.59,46.99 19.88,48.7 U2.5 ; v2(37.97,37.48) 38.23,37.22 R30.2
  BOTTOM w0.203: v2(37.97,37.48) 37.58,37.48 36.07,38.99 21.59,38.99 v2(21.46,39.12)
FTDI_QUAD_C_U_RTS_BP: length 33
  TOP w0.203: R17.2 20.57,59.44 20.95,59.82 22.86,59.82 23.22,59.46 23.22,54.99 26.14,52.07 v2(27.69,52.07)
  BOTTOM w0.203: v2(27.69,52.07) 37.72,52.07 39.62,50.16 J7.7
FTDI_QUAD_C_U_RX_3V3: length 29.6
  TOP w0.203: v2(22.61,39.6) 22.61,46.61 20.53,48.68 U2.6 ; R31.2 39.12,36.67 v2(39.12,37.48)
  BOTTOM w0.203: v2(39.12,37.48) 37.2,39.4 22.81,39.4 v2(22.61,39.6)
FTDI_QUAD_C_U_RX_BP: length 22.9
  TOP w0.203: R18.1 21.19,57.03 21.19,57.02 21.01,56.84 21,56.84 20.53,56.38 U2.11 20.53,54.19 19.94,53.59 v2(16.26,53.59)
  BOTTOM w0.203: v2(16.26,53.59) 15.88,53.21 6.48,53.21 5.71,53.98 3.94,53.98 2.67,52.7 J8.5
FTDI_QUAD_C_U_TX_3V3: length 33.2
  TOP w0.203: R32.2 40.26,36.67 v2(40.26,37.19) ; U2.4 19.23,48.77 20.68,47.33 20.68,38.38 v2(20.7,38.35)
  BOTTOM w0.203: v2(20.7,38.35) 35.69,38.35 37.17,36.87 39.94,36.87 v2(40.26,37.19)
FTDI_QUAD_C_U_TX_BP: length 25.3
  TOP w0.203: v2(19.18,60.07) 19.56,59.69 R16.2
  BOTTOM w0.203: v2(19.18,60.07) 19.18,55.5 16.38,52.7 6.86,52.7 5.46,51.31 3.81,51.31 2.67,50.16 J8.7
FTDI_QUAD_D_U_RX_3V3: length 36.3
  TOP w0.203: U1.6 12.91,48.17 v2(13.21,47.88) ; R45.2 29.08,25.65 28.19,26.54 28.19,33.66 24.38,37.47 v2(24.38,45.47)
  BOTTOM w0.203: v2(13.21,47.88) 15.14,45.95 23.9,45.95 v2(24.38,45.47)
FTDI_QUAD_D_U_RX_BP: length 66.1
  TOP w0.203: R22.2 12.91,57.09 U1.11 12.91,54.02 14.99,51.94 14.99,45.72 17.02,43.69 J3.3
  BOTTOM w0.203: J3.3 15.75,38.61 15.75,33.66 16.38,33.02 19.15,33.02 21.78,35.65 39.82,35.65 41.91,33.55 42.42,33.55 42.93,34.06 42.93,41.6 43.87,42.55 J7.13
FTDI_QUAD_D_U_TX_3V3: length 38.1
  TOP w0.203: U1.4 11.61,48.57 11.18,48.13 v2(11.18,45.72) ; R38.2 33.27,35.02 v2(33.27,43.59)
  BOTTOM w0.203: v2(33.27,43.59) 33.07,43.38 25.2,43.38 23.04,45.54 11.35,45.54 v2(11.18,45.72)
LED1: length 40.8
  TOP w0.203: 44.28,26.51 v2(42.67,26.51) ; R25.1 38.95,48.04 42.95,44.04 49.17,44.04 50.04,43.18 50.04,32.64 v2(49.66,32.26)
  BOTTOM w0.203: v2(49.66,32.26) 49.66,29.69 46.28,26.31 42.86,26.31 v2(42.67,26.51)
LED2: length 41.1
  TOP w0.203: 44.28,27.01 43.22,27.01 v2(42.42,27.81) ; R24.1 38.35,53.59 37.85,53.09 37.85,48.32 42.53,43.64 49.01,43.64 49.5,43.15 49.5,33.72 v2(49.43,33.66)
  BOTTOM w0.203: v2(49.43,33.66) 49.43,33.45 46.96,30.99 45.59,30.99 v2(42.42,27.81)
LP_MATE_EN: length 29.6
  TOP w0.203: J2.2 30.1,51.56 28.83,52.83 25.95,52.83 23.63,55.16 23.63,59.44 24.38,60.2 25.53,60.2 26.04,59.69 v2(26.04,59.44) R12.2 ; R6.2 v2(33.66,60.2)
  BOTTOM w0.203: v2(33.66,60.2) 32.79,59.33 26.14,59.33 v2(26.04,59.44)
LP_UART_DIS: length 21.4
  TOP w0.203: J1.2 18.8,46.35 16.13,46.35 15.51,46.98 15.51,53.45 15.14,53.82 15.14,58.83 16.1,59.79 18.06,59.79 18.54,59.31 R15.2
USB_1V8: length 15.1
  TOP w0.254: U7.64 30.52,20.51 C20.1 30.46,19.96 30.86,19.56 v2(31.24,19.56) ; v2(30.99,29.08) 30.46,28.56 C13.1 30.52,28.01 U7.49 ; v2(42.11,15.73) C24.1 40.36,16.77 U7.12 ; U7.37 40.36,32.38 C11.1 40.89,32.4 41.15,32.15 v2(41.15,32)
USB_3V3: length 76.9
  TOP w0.203: R59.1 v2(3.05,24) 3.58,24 R61.1 ; R62.1 15.24,31.75 v2(14.99,32) ; v2(16,17.14) 15.97,17.17 R68.1 ; v2(24,23.88) 24.13,24 R46.2 ; R58.1 v2(1.91,24) ; R49.2 27.81,23.62 v2(28.45,22.99) ; R47.2 v2(25.53,24)
  TOP w0.254: v2(37.21,31.88) 37.74,32.4 C10.1 37.86,32.39 U7.42 ; 44.28,22.01 46.66,22.01 C19.1 46.75,22.59 v2(46.35,22.99) ; v2(46.23,28.33) 46.75,27.81 C14.1 45.59,27.69 45.41,27.51 44.28,27.51 ; v2(30.46,23.79) C16.1 30.47,24.51 U7.56 ; U7.9 38.86,15.64 C23.1 C29.1 38.48,13.82 v2(38.48,13.72) ; v2(36.3,13.55) C28.1 C22.1 36.36,15.55 U7.4 ; U9.4 12.08,21.36 13.72,23 v2(13.72,23.11) ; U9.31 13.09,30.24 C18.1 v2(12.19,30.24) ; U9.14 19.03,22.01 C27.1 v2(19.07,22.73) ; R42.2 v2(28.8,26.8)
  TOP w0.381: U4.3 33.82,50.75 33.54,51.04 33.46,51.04 33.17,50.75 ; U3.2 25.55,50.88 25.4,51.04 25.19,51.04 24.9,50.75 U3.1 24.89,49.74 C7.1 v2(24.01,47.99) ; v2(8.62,33.75) C15.1 8.65,34.51 U6.1 9.66,35.51 9.95,35.8 10.16,35.8 10.31,35.64 U6.2 ; v2(24.26,33.91) 24.51,34.16 C9.1 25.31,34.06 U5.8 ; v2(1.02,32.38) C17.1 1.89,31.73 2.05,31.89 U8.8 ; 33.17,50.75 32.89,51.04 32.69,51.04 32.52,50.87 U4.1 32.52,48 C8.1 v2(33.27,47.99) ; 33.17,50.75 U4.2 ; v2(8.87,48.11) C5.1 9.66,48.13 U1.1 9.66,50.75 9.95,51.04 10.16,51.04 10.31,50.88 U1.2 ; U2.2 17.93,50.9 17.78,51.05 17.53,51.05 17.28,50.81 U2.1 17.27,49.74 C6.1 16.66,47.99 v2(16.38,48.26)
  TOP w0.505: 31.55,3.89 R73.2 ; 30.4,3.96 C34.1
  vias: v2(29.54,3.28) v2(29.64,1.91) v2(31.29,3.28) v2(31.37,1.85)
N01286: length 3.5
  TOP w0.203: U5.4 27.26,26.71 27.78,26.19 R44.1 27.81,25.63 R49.1
N01352: length 12.7
  TOP w0.203: U7.62 31.32,21.51 31.11,21.72 28.07,21.72 26.24,23.55 26.24,25.58 26.06,25.75 R47.1 25.53,26.23 25.96,26.67 U5.2
N01364: length 3.2
  TOP w0.203: R65.2 37.59,16.18 37.36,16.42 U7.6
N01384: length 10
  TOP w0.203: U7.2 35.36,17.58 34.8,17.02 31.75,17.02 30.12,18.65 C21.1 29.11,19.01 Y1.3
N01506: length 15
  TOP w0.203: U5.1 25.31,27.22 24.77,26.67 24.51,26.67 24.13,26.29 R46.1 24.65,25.75 24.89,25.51 24.89,22.99 26.57,21.31 30.89,21.31 31.19,21.01 U7.63
N01570: length 16.1
  TOP w0.203: Y1.1 23.75,15.01 C31.1 33.34,14.99 35.86,17.5 U7.3
N01960: length 11.1
  TOP w0.203: U5.3 26.61,26.45 26.83,26.24 R44.2 26.83,23.61 28.31,22.12 31.28,22.12 31.4,22.01 U7.61
N02002: length 4.2
  TOP w0.203: R63.2 42.93,16.13 42.42,16.64 41.66,16.64 40.86,17.43 U7.13
N02098: length 20.9
  TOP w0.254: U7.8 38.36,19.94 38.61,20.19
  TOP w0.4: v2(38.76,21.2) 38.61,21.05 38.61,20.19 ; v2(40.25,7.12) 40.02,6.89 40.02,5.49 39.99,5.46 J6.3
  BOTTOM w0.4: v2(38.76,21.2) 38.4,20.84 38.4,17.58 40.01,15.98 40.01,13.33 40.01,13.33 40.01,7.36 v2(40.25,7.12)
N02410: length 23
  TOP w0.203: R42.1 31.16,27.51 U7.50 34.22,27.51 40.04,21.65 v2(40.7,21.65) ; R64.1 v2(44.73,14.76)
  BOTTOM w0.203: v2(44.73,14.76) 44.73,18.77 41.85,21.65 v2(40.7,21.65)
N02574: length 4.7
  TOP w0.203: U7.14 41.36,17.51 41.82,17.04 43.08,17.04 43.94,16.18 R64.2
N226931: length 3.8
  TOP w0.381: 41.29,5.06 J6.5
  TOP w0.505: 41.29,5.06 41.29,5.06 41.29,6.16 42.33,7.2 FB2.2
N227919: length 20.9
  TOP w0.254: 37.59,20.19 37.86,19.93 U7.7
  TOP w0.4: J6.2 39.34,5.46 39.32,5.49 39.32,6.89 v2(39.09,7.12) ; 37.59,20.19 37.59,20.95 v2(37.33,21.2)
  BOTTOM w0.4: v2(37.33,21.2) 37.7,20.84 37.7,17.29 39.31,15.69 39.31,7.33 v2(39.09,7.12)
N230138: length 3.5
  TOP w0.381: J5.5 13.81,5.05
  TOP w0.505: FB3.2 14.94,6.97 14.94,6.17 13.81,5.05
N230650: length 3.3
  TOP w0.203: U8.4 4.76,26.36 5.05,26.06 R56.1 R61.2
N230686: length 18.2
  TOP w0.203: v2(10.79,25.27) 11.28,24.79 11.28,22.45 10.58,21.76 U9.1 ; R59.2 3.05,26.16 3.46,26.57 U8.2 v2(3.46,29.18)
  BOTTOM w0.203: v2(10.79,25.27) 8.13,27.94 4.7,27.94 v2(3.46,29.18)
N230722: length 19.9
  TOP w0.203: U8.1 2.81,26.69 1.91,25.78 R58.2 1.27,25.75 1.04,25.53 1.04,19.66 2.03,18.67 7.24,18.67 7.75,19.18 7.75,20.83 8.43,21.51 U9.48
N230850: length 18.5
  TOP w0.203: U9.2 11.08,21.69 11.68,22.29 11.68,24.89 v2(12.06,25.27) ; v2(5.21,29.21) 4.45,29.21 4.11,28.87 U8.3 4.11,25.67 R56.2
  BOTTOM w0.203: v2(5.21,29.21) 8.13,29.21 v2(12.06,25.27)
N232459: length 7.8
  TOP w0.203: Y2.1 4.24,19.82 C26.1 6.59,22.04 8.06,23.51 U9.44
N232466: length 10.1
  TOP w0.203: U9.43 7.99,24.01 7.61,23.63 3.8,23.63 3.48,23.31 3.48,22.41 3.29,22.23 3.03,22.23 C25.1 2.84,20.05 Y2.2
N232899: length 2.6
  TOP w0.4: J5.2 11.86,6.33 R71.1
N233111: length 2.6
  TOP w0.4: R72.1 12.51,6.32 J5.3
N233117: length 18.7
  TOP w0.254: v2(14.35,21.72) 14.35,21.41 14.1,21.16 14.1,20.96 14.08,20.94 U9.8
  TOP w0.4: v2(11.56,8.28) R71.2
  BOTTOM w0.4: v2(14.35,21.72) 14.19,21.56 14.19,19.55 13.56,18.92 13.56,8.17 13.09,7.7 12.51,7.7 11.93,8.28 v2(11.56,8.28)
N233261: length 23
  TOP w0.203: R67.1 9.92,19.31 v2(9.92,20.73)
  TOP w0.254: v2(13.34,21.72) 13.34,21.39 13.57,21.16 13.57,20.68 13.58,20.66 U9.7
  TOP w0.4: R72.2 12.83,8.38 v2(12.8,8.41)
  BOTTOM w0.203: v2(13.34,21.72) 12.95,21.34 10.53,21.34 v2(9.92,20.73)
  BOTTOM w0.4: v2(13.34,21.72) 13.49,21.56 13.49,19.84 12.86,19.21 12.86,8.46 12.81,8.41 v2(12.8,8.41)
N233354: length 2
  TOP w0.203: U9.6 13.08,20.13 C32.1
N233745: length 4.3
  TOP w0.203: U9.46 8.16,22.51 7.08,21.43 R66.2 7.09,20.82 C30.1
N234481: length 2.2
  TOP w0.203: R67.2 12.58,18.71 U9.5
N234666: length 2
  TOP w0.203: R62.2 15.59,29.91 U9.26
N234693: length 2.1
  TOP w0.203: U9.10 15.08,19.05 15.09,19.05 15.09,18.54 15.08,18.54 15.08,18.29 R68.2
N238775: length 2.5
  TOP w0.203: R48.1 46.65,25.01 44.28,25.01
N238779: length 2.6
  TOP w0.203: 44.28,25.51 46.36,25.51 R43.1
N238807: length 2.9
  TOP w0.203: R41.1 46.1,29.08 45.02,28.01 44.28,28.01
N238860: length 5.9
  TOP w0.203: U7.38 39.86,31.88 39.75,31.99 39.75,34.7 R32.1
N238864: length 5.5
  TOP w0.203: R31.1 39.34,35.44 39.34,29.95 U7.39
N238868: length 5.8
  TOP w0.203: U7.40 38.89,29.96 38.89,34.8 R30.1
N238872: length 6.2
  TOP w0.203: U7.41 38.36,31.86 38.48,31.99 38.48,34.06 R29.1
N238924: length 2.6
  TOP w0.203: R38.1 34.86,32.48 U7.48
N238928: length 2.8
  TOP w0.203: U7.52 31.3,26.51 R45.1
N239386: length 2.6
  TOP w0.203: R39.1 41.86,32.11 U7.34
N272217: length 11.3
  TOP w0.203: R53.2 6.63,27.33 10.54,31.24 11.43,31.24 13.59,33.4 13.59,34.49 U6.7
N292019: length 5.9
  TOP w0.203: R14.1 R15.1 18.58,57.39 U2.14 18.58,54.41 18.38,54.21 18.03,54.21 17.93,54.31 U2.15
N292933: length 1.5
  TOP w0.203: D1.1 R24.2
N292961: length 1.5
  TOP w0.203: D2.1 R25.2
N294895: length 5.8
  TOP w0.203: R7.1 R6.1 33.74,58.24 33.74,57.23 33.53,57.02 33.53,56.76 ; U4.15 33.17,56.4 33.53,56.76 ; 33.53,56.76 33.82,56.46 U4.14
N295733: length 5.4
  TOP w0.203: 26.04,56.9 R12.1 R13.1 ; 26.04,56.9 26.2,56.73 U3.14 ; 26.04,56.9 25.55,56.41 U3.15
N296706: length 3.4
  TOP w0.203: 10.67,56.74 10.67,56.72 10.96,56.42 U1.14 ; 10.67,56.74 R20.1 ; 10.67,56.74 10.31,56.39 U1.15
N300466: length 2.8
  TOP w0.203: 44.28,21.51 46.09,21.51 R50.1
N300468: length 3
  TOP w0.203: R51.1 45.44,21.01 44.28,21.01
N300470: length 3.5
  TOP w0.203: R54.1 45.85,18.54 44.28,20.11 44.28,20.51
N300472: length 4.9
  TOP w0.203: R60.1 43.94,17.4 42.76,18.58 U7.16
N302094: length 2
  TOP w0.203: R53.1 7.59,26.57 8.16,26.01 U9.39
N302821: length 1.9
  TOP w0.203: R23.1 13.56,56.77 U1.10
N310009: length 4.1
  TOP w0.203: R33.1 10.16,41.53 10.31,41.38 ; U6.14 10.97,40.17 10.97,41.39 10.83,41.53 10.47,41.53 10.31,41.38 ; 10.31,41.38 U6.15
N310225: length 16.3
  TOP w0.203: U6.6 12.91,35.62 13.21,35.92 14.33,35.92 14.82,35.43 14.82,33.18 v2(19.05,28.96) ; R55.2 v2(20.83,25.91)
  BOTTOM w0.203: v2(19.05,28.96) 19.05,27.69 v2(20.83,25.91)
N314694: length 1.7
  TOP w0.203: U1.5 12.26,48.18 R26.1
N325704: length 2.9
  TOP w0.203: U7.33 42.36,31.46 R40.1
N329899: length 15.9
  TOP w0.203: R52.2 19.91,29.11 15.23,33.79 15.23,35.59 14.5,36.32 12.06,36.32 11.61,35.87 U6.4
N329904: length 12.4
  TOP w0.203: U6.5 12.26,33.47 10.79,32 10.29,32 5.97,27.69 5.97,25.78 6.22,25.53 R57.2
N334866: length 2.3
  TOP w0.203: U2.12 19.88,56.73 20.57,57.42 R17.1
N372295: length 2.2
  TOP w0.203: U6.13 11.61,41.76 R34.1
N372693: length 1.5
  TOP w0.203: R52.1 18.91,27.01 U9.24
N372697: length 1.8
  TOP w0.203: U9.23 18.45,26.51 18.95,26.01 R55.1
N381832: length 2.1
  TOP w0.203: R35.1 12.26,42.12 U6.12
N381852: length 1.6
  TOP w0.203: R57.1 9.19,25.53 U9.40
N393401: length 1.8
  TOP w0.203: R21.1 11.61,57.11 U1.13
N393405: length 1.3
  TOP w0.203: R21.2 TP1.1
N393465: length 3.6
  TOP w0.203: R2.1 28.32,57.8 27.74,57.22 27.63,57.22 26.85,56.44 U3.13
N393469: length 3.7
  TOP w0.203: U3.12 27.5,56.41 28.73,57.63 28.73,57.7 29.34,58.31 R3.1
N393541: length 2.2
  TOP w0.203: U2.13 19.23,57.11 R16.1
N393687: length 4.8
  TOP w0.203: R11.1 38.19,57.14 37.1,57.14 36.42,56.46 U4.10
N393689: length 4.2
  TOP w0.203: R10.1 37.45,57.54 36.93,57.54 35.77,56.39 U4.11
N393691: length 3.8
  TOP w0.203: U4.12 35.12,56.42 36.26,57.56 36.32,57.56 R9.1
N393693: length 3.5
  TOP w0.203: U4.13 34.47,56.46 35.49,57.48 35.49,57.87 R8.1
N407737: length 3.2
  TOP w0.762: J8.2 5.08,58.33 R1.1
N408139: length 30
  TOP w0.203: R74.1 42.16,37.47 v2(41.66,37.97)
  BOTTOM w0.203: 17.04,34.77 J3.1 18.45,36.23 18.45,38.39 20.32,40.26 37.21,40.26 39.5,37.97 v2(41.66,37.97)
N408257:
  vias: v1(18.92,6.99) v1(20.32,6.99)
N408297: length 3.9
  TOP w0.203: R70.2 31.55,6.73 R73.1 31.54,5.72 C34.2 29.8,6.32 U10.5
N408485: length 1.7
  TOP w0.203: R69.2 32.4,12.14 D3.1
N415889: length 1.2
  TOP w0.203: R35.2 TP2.1
N437475: length 2.8
  TOP w0.203: J7.19 43.66,34.92 R75.2
N437479: length 2.4
  TOP w0.203: J7.17 R74.2

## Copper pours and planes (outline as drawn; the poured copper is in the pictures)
GND on TOP: 0.56,6.78 0.53,6.81 0.53,65.18 0.76,65.41 50.04,65.41 50.29,65.15 50.29,60.83 50.27,60.81 50.27,0.89 49.89,0.51 0.76,0.51 0.51,0.76 0.51,6.73 ; 22 cut-outs
GND on BOTTOM: 0.56,6.78 0.53,6.81 0.53,65.18 0.76,65.41 49.78,65.41 50.29,64.9 50.29,60.83 50.27,60.81 50.27,0.74 50.04,0.51 26.42,0.51 26.42,5.21 28.45,7.24 31.75,7.24 31.88,7.11 36.45,7.11 37.47,8.13 37.47,11.43 35.43,13.46 23.37,13.46 20.07,10.16 20.07,9.02 19.68,8.64 18.41,8.64 17.02,7.24 17.02,6.1 18.03,5.08 20.07,5.08 20.19,4.95 20.19,0.76 20.07,0.64 16.51,0.64 16.38,0.51 0.76,0.51 0.51,0.76 0.51,6.73 ; 14 cut-outs
GND on GND: 0.62,6.72 0.53,6.81 0.53,65.18 0.76,65.41 49.78,65.41 50.29,64.9 50.29,62.28 50.27,62.26 50.27,6.86 50.29,6.83 50.29,0.76 50.04,0.51 1.14,0.51 0.62,1.03
VCC_5V on TOP: 9.4,62.48 8.26,62.48 7.87,62.1 7.87,58.67 8.13,58.42 9.02,58.42 9.65,59.05 9.65,62.23
VCC_5V on BOTTOM: 9.4,62.48 8.26,62.48 7.87,62.1 7.87,58.67 8.13,58.42 9.02,58.42 9.65,59.05 9.65,62.1 9.4,62.36
VCC_BP on PWR: 29.08,9.65 29.08,5.21 29.97,4.32 35.05,4.32 35.56,3.81 35.56,0.89 35.81,0.64 50.04,0.64 50.29,0.89 50.29,6.35 50.04,6.6 50.16,6.73 50.16,60.91 50.14,60.93 50.14,62.26 50.16,62.28 50.16,64.9 49.66,65.41 1.02,65.41 0.76,65.15 0.76,61.09 0.64,60.96 0.64,38.86 0.76,38.73 17.14,38.73 17.78,39.37 17.78,44.32 17.4,44.7 8.26,44.7 7.62,45.34 7.62,51.31 8.76,52.45 23.5,52.45 26.42,49.53 42.55,49.53 43.69,48.39 43.69,30.86 43.81,30.73 46.99,30.73 47.24,30.48 47.24,12.06 45.59,10.41 29.84,10.41
VCC_USB5V_DUAL on TOP: 10.49,10.62 7.44,10.62 7.24,10.41 7.24,8.51 7.49,8.26 10.24,8.26 10.59,8.61 10.59,10.52
VCC_USB5V_DUAL on TOP: 19.84,2.67 17.58,2.67 17.2,2.29 17.2,0.69 17.32,0.56 19.96,0.56 20.09,0.69 20.09,2.41
VCC_USB5V_DUAL on PWR: 0.89,22.23 0.64,21.97 0.64,0.89 0.89,0.64 19.3,0.64 19.43,0.76 19.43,7.24 15.11,11.56 15.11,21.59 14.61,22.1 13.08,22.1 12.7,22.48 12.7,24.13 12.45,24.38 7.37,24.38 7.24,24.26 7.24,22.61 6.86,22.23
VCC_USB5V_QUAD on TOP: 33.77,10.88 33.48,10.59 33.48,8.94 34.01,8.41 38.71,8.41 39.17,8.86 39.17,10.44 38.72,10.88
VCC_USB5V_QUAD on TOP: 23.04,2.62 20.93,2.62 20.62,2.31 20.62,0.79 20.88,0.53 23.14,0.53 23.22,0.61 23.22,2.44
VCC_USB5V_QUAD on BOTTOM: 20.57,4.57 20.57,1.02 21.08,0.51 25.4,0.51 26.04,1.14 26.04,5.46 27.94,7.37 27.94,7.49 28.07,7.62 36.2,7.62 37.08,8.51 37.08,11.18 35.31,12.95 23.75,12.95 21.46,10.67 21.46,5.46
USB_1V8 on PWR: 30.23,28.07 31.11,28.07 31.5,27.69 31.5,20.7 30.86,20.07 30.86,15.11 31.24,14.73 41.91,14.73 42.55,15.37 42.55,24.77 42.16,25.15 36.58,25.15 36.07,25.65 36.07,32.89 36.58,33.4 39.37,33.4 39.88,32.89 39.88,30.99 40.13,30.73 43.05,30.73 43.18,30.86 43.18,35.43 42.8,35.81 30.1,35.81 29.97,35.69 29.97,28.32
USB_3V3 on TOP: 28.32,7.62 27.48,7.62 27.28,7.42 27.28,0.94 27.41,0.81 33.78,0.81 34.85,1.88 34.85,3.43 34.37,3.91 32.82,3.91 32.66,4.06 29.84,4.06 29.69,4.22 29.69,4.78 29.36,5.11 28.63,5.11 28.42,5.31 28.42,7.52
USB_3V3 on PWR: 0.64,38.1 0.64,22.99 0.89,22.73 6.6,22.73 6.73,22.86 6.73,24.51 7.11,24.89 12.7,24.89 13.21,24.38 13.21,22.73 13.34,22.61 14.86,22.61 15.62,21.84 15.62,11.94 19.94,7.62 19.94,0.76 20.07,0.64 34.8,0.64 35.05,0.89 35.05,3.43 34.67,3.81 29.59,3.81 28.57,4.83 28.57,9.91 29.59,10.92 45.21,10.92 46.74,12.45 46.74,29.97 46.48,30.23 39.88,30.23 39.37,30.73 39.37,32.64 39.12,32.89 36.83,32.89 36.58,32.64 36.58,26.04 36.96,25.65 42.67,25.65 43.05,25.27 43.05,14.86 42.42,14.22 30.86,14.22 30.35,14.73 30.35,20.32 30.99,20.95 30.99,27.3 30.73,27.56 29.97,27.56 29.46,28.07 29.46,35.94 29.84,36.32 43.05,36.32 43.18,36.45 43.18,48.13 42.29,49.02 26.16,49.02 23.24,51.94 9.02,51.94 8.13,51.05 8.13,45.59 8.51,45.21 17.78,45.21 18.29,44.7 18.29,39.12 17.4,38.23 0.76,38.23
N226875 on TOP: 38.2,7.9 35.43,7.9 35.18,7.65 35.18,3.99 35.81,3.35 38.81,3.35 38.99,3.53 38.99,5.77 38.35,6.4 38.35,7.75
N230114 on TOP: 10.11,7.67 8.05,7.67 7.73,7.35 7.73,7.34 7.39,7 7.39,3.98 8.15,3.21 11.24,3.21 11.46,3.43 11.46,5.44 10.39,6.5 10.39,7.39
N408257 on TOP: 20.45,7.75 20.07,8.13 20.07,11.43 19.56,11.94 18.16,11.94 17.91,11.68 17.91,4.9 18.39,4.42 24.74,4.42 25.7,5.38 25.7,7.47 25.43,7.75
N408257 on BOTTOM: 20.7,8.13 20.32,8.13 20.07,8.38 20.07,11.68 19.94,11.81 17.78,11.81 17.4,11.43 17.4,6.1 18.03,5.46 20.7,5.46 20.95,5.71 20.95,7.87

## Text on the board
Ref Des/Silkscreen Bottom: Rev 3.0 | MODEL: CC31XXEMUBOOST
User.Comments: UNLESS OTHERWISE SPECIFIED | ALL DIMENSIONS ARE IN | INCHES | MILLIMETERS | REV 3.0 | FEBRUARY 07 2014 | DATE | PART NUMBER | CC31XXEMUBOOST | CC31XX_FTDI_DBG_3.0 | A | FABRICATION DRAWING | TEXAS INSTRUMENTS | X
Ref Des/Silkscreen Top: P1 | VCC | HIB | CLK | RX | TX | GND | P3 | RT3/MAC | NWP | 5V | SPI/GPIO/UART/NWP | RT3 | WTX | P4 | RTS | CTS | MOSI | MISO | MODE | IRQ | RST | CS | P2 | LP | BP | DISABLE | LP_UART | ENABLE | LP_MATE | VCC_BP | CC31XXEMUBOOST | Rev 3.0
PAGE_OUTLINE: CAD | DATA | DO NOT MANUALLY | UPDATE | D | C | B | A | 8 | 7 | 6 | 5 | 4 | 3 | 2 | 1
User.5: FABRICATION DRAWING
User.6: ASSEMBLY PRIMARY SIDE
User.7: DATE:FEBRUARY 07 2014 | PART NO/CARD REF: | FILM LAYER: | TESSOLVE | CC31XXEMUBOOST Rev 3.0 | DESIGNED BY: | COMPANY NAME : TEXAS INSTRUMENTS
User.8: PRIMARY SIDE
User.9: LAYER 2 (GND)
User.10: LAYER 3 (PWR)
User.13: LAYER 4(BOTTOM SIDE)"
User.14: PRIMARY SIDE SILKSCREEN
User.15: SECONDARY SIDE  SILKSCREEN
User.16: PRIMARY SIDE PASTE LAYER
User.17: SECONDARY SIDE PASTE LAYER
User.18: PRIMARY SIDE SOLDERMASK
User.19: SECONDARY SIDE SOLDERMASK
User.20: OUTLINE
User.23: ASSEMBLY SECONDARY SIDE
User.24: 5.   ALL VIAS TO BE TENTED. | GENERAL NOTES-- UNLESS OTHERWISE SPECIFIED: | 1.   FABRICATE PER IPC-6012A CLASS 2 | 2.   SURFACE FINISH   :  ENIG | 3.   MATERIAL; FR4 | 4.   COPPER WT: 1 Oz | BOARD THICKNESS : 1.4 mm(+/- 0.1mm) | 6.   SOLDER MASK CLEARANCE IS GIVEN | 7. SOLDER MASK COLOUR : RED | SAME AS PAD SIZE EXCEPT FIDUCIAL | VENDOR SHALL MODIFY THE MASK CLEARANCE AS PER | THE REQUIRED MANUFACTURING TOLERANCEANCE | STACK UP | NO SCALE | SECTION A-A | LAYER 03 - PWR PLANE | LAYER 01-TOP SIDE | LAYER 02 - GND PLANE | LAYER 04 - BOTTOM
User.26: FIGURE | SIZE | 12.0 | 20.0 | 38.0 | 125.9843 | 33.4646x21.6535 | 45.2756x19.685 | DRILL CHART: TOP to BOTTOM | ALL UNITS ARE IN MILS | TOLERANCE | +3.0/-3.0 | +2.0/-2.0 | PLATED | NON-PLATED | QTY | 215 | 6 | 51 | 4
